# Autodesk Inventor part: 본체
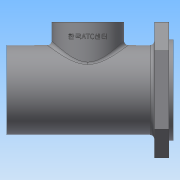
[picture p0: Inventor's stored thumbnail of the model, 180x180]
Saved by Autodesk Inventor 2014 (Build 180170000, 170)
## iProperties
Created: 2017-10
Part Number: 본체
Material: 일반
Document SubType Name: Modeling
Designer: net
Density: 1 g/cm^3
Appearance: 기본값
Mass: 274.888 g
Surface Area: 660.032 cm^2
Volume: 274.888 cm^3
Author: net
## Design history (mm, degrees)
sketch "스케치1"
  geometry: L1 (-58, 47)-(58, 47); L2 (58, 47)-(58, -47); L3 (58, -47)-(-58, -47); L4 (-58, -47)-(-58, 47); L5 (-46, 20)-(-46, -20); L6 (-42, 20)-(-42, -20); L7 (-50, -20)-(-50, 20); L8 (46, 20)-(46, -20); L9 (50, 20)-(50, -20); L10 (42, -20)-(42, 20); A1 r 4 centre (-46, 20) between (-42, 20) and (-50, 20); A2 r 4 centre (-46, -20) between (-50, -20) and (-42, -20); A3 r 4 centre (46, 20) between (50, 20) and (42, 20); A4 r 4 centre (46, -20) between (42, -20) and (50, -20); 5 further points
  constraints: 24 end point, 8 point on circle, 8 tangent, 7 parallel, 4 centre point, 4 midpoint, 3 horizontal alignment, 1 equal radius, 1 horizontal, 1 perpendicular, 1 vertical alignment
  dimensions: "d0" = 116 distance of L2.end L3.end; "d1" = 94 distance of L1.end L2.end; "d2" = 46 distance of point (0, 0) point (-46, 0); "d3" = 40 distance of L5.start L5.end; "d4" = 4 radius of A1; "d7" = 46 distance of point (46, 0) point (0, 0)
extrude "돌출1" new body sketch "스케치1" distance "d5" = 10; taper "d6" = 0 deg
extrude "돌출2" cut sketch "스케치1" stored distance "d8" = 10; taper "d9" = 0 deg
chamfer "모따기1" distance "d10" = 20; stored, may be unused: second distance "d11" = 2, angle "d12" = 45 deg
sketch "스케치2"
  geometry: C1 r 31 at (0, 0); 1 further point
  constraints: 1 centre point, 1 coincident
  dimensions: "d13" = 62 diameter of C1
extrude "돌출3" join sketch "스케치2" distance "d14" = 102; taper "d15" = 0 deg
sketch "스케치3"
  geometry: C1 r 35 at (0, 0); 1 further point
  constraints: 1 centre point, 1 coincident
  dimensions: "d16" = 70 diameter of C1
extrude "돌출4" join sketch "스케치3" distance "d17" = 3; taper "d18" = 0 deg
sketch "스케치4"
  geometry: L1 (31, 0)-(31, -102) reference; L2 (-31, -102)-(31, -102) reference; L3 (35, 13)-(-35, 13) reference; L4 (0, -102)-(0, 13); L5 (0, -93)-(24, -93); L6 (24, -93)-(24, -90); L7 (24, -90)-(20, -90); L8 (20, -90)-(20, -81); L9 (20, -81)-(17.5, -81); L10 (17.5, -81)-(17.5, -77.75); L11 (17.5, -77.75)-(18.5, -77.75); L12 (18.5, -77.75)-(18.5, -76); L13 (26, -65)-(26, -27); L14 (26, -27)-(17.5, -27); L15 (17.5, -27)-(17.5, -16); L16 (17.5, -16)-(16.5, -16); L17 (16.5, -16)-(16.5, -11); L18 (16.5, -11)-(10, -11); L19 (10, -11)-(10, -8.3); L20 (10, -8.3)-(12.5, -8.3); L21 (12.5, -8.3)-(12.5, -1.7); L22 (18.5, -76)-(17.5, -76); L23 (17.5, -76)-(17.5, -65); L24 (17.5, -65)-(26, -65); L25 (12.5, -1.7)-(12.904, -1); L26 (12.904, -1)-(16, -1); L27 (16, -1)-(22, 13); 2 further points
  constraints: 48 end point, 16 parallel, 3 midpoint, 3 perpendicular, 2 point on line, 1 horizontal
  dimensions: "d19" = 3 distance of L5.end L6.end; "d20" = 9 distance of L7.end L8.end; "d21" = 48 diameter of L6 L4; "d22" = 40 diameter of L8 L4; "d23" = 9 distance between parallel lines of L2 L5; "d24" = 35 diameter of L10 L4; "d25" = 37 diameter of L12 L4; "d28" = 3.25 distance of L9.end L10.end; "d29" = 38 distance of L13.start L13.end; "d30" = 52 diameter of L13 L4; "d31" = 35 diameter of L15 L4; "d32" = 11 distance of L14.end L15.end; "d33" = 2.7 distance of L18.end L19.end; "d35" = 20 diameter of L19 L4; "d36" = 25 diameter of L21 L4; "d39" = 33 diameter of L17 L4; "d40" = 5 distance of L16.end L17.end; "d42" = 1.75 distance of L11.end L12.end; "d43" = 11 distance of L22.end L23.end; "d44" = 35 diameter of L23 L4; "d47" = 0.7 vertical distance of L21.end L25.end; "d48" = 7.3 vertical distance of L25.end L20.end; "d50" = 32 diameter of L26.end L4; "d51" = 44 diameter of L27.end L4
revolve "회전1" sketch "스케치4" stored, may be unused: angle "d52" = 90 deg
hole "구멍1" diameter "d55" = 37.129; stored, may be unused: countersink angle "d59" = 90 deg, drill point angle "d61" = 118 deg; dims "d53" = 10, "d54" = 10, "d56" = 9, "d57" = 4, "d58" = 2, "d60" = 9
node "작업 평면1"
sketch "스케치5"
  geometry: L1 (38, 0)-(-38, 0) reference; L2 (-31, -102)-(31, -102) reference; C1 r 25 at (0, -46); C2 r 16 at (0, -46); 2 further points
  constraints: 2 centre point, 1 coincident, 1 midpoint, 1 vertical alignment
  dimensions: "d63" = 50 diameter of C1; "d64" = 32 diameter of C2; "d65" = 31 distance edge to line of C1 L2
extrude "돌출5" join sketch "스케치5" stored distance "d66" = 3; taper "d67" = 0 deg
extrude "돌출6" cut sketch "스케치5" stored distance "d68" = 3; taper "d69" = 0 deg
sketch "스케치6"
  geometry: C1 r 16 at (0, 0) reference; 3 further points
  constraints: 2 horizontal alignment
  dimensions: "d70" = 41 distance of point (20.5, 0) point (-20.5, 0); "d71" = 20.5 distance of point (-20.5, 0) C1.centre
hole "구멍2" sketch "스케치6" at (-20.5, 0), (20.5, 0) diameter "d72" = 2.459; stored, may be unused: countersink angle "d76" = 90 deg, drill point angle "d78" = 118 deg; dims "d73" = 6, "d74" = 4, "d75" = 2, "d77" = 8
node "작업 평면2"
sketch "스케치7"
  geometry: L1 (16, -56)-(78, -56) reference; L2 (0, -25)-(0, 25) reference; 2 further points
  constraints: 1 other
  dimensions: "d79" = 56 distance from line of L1 point (10, 0); "d80" = 10 distance from line of point (10, 0) L2
feature "엠보싱1" sketch "스케치7" dims "d0" = 116, "d1" = 94, "d2" = 46, "d3" = 40, "d4" = 4, "d7" = 46, "d81" = 0.5, "d82" = 0
fillet "모깎기1" dims "d83" = 0.3
fillet "모깎기2" dims "d84" = 0.3
fillet "모깎기3" dims "d85" = 3
fillet "모깎기4" dims "d86" = 3
fillet "모깎기5" dims "d87" = 3
chamfer "모따기2" distance "d88" = 1; stored, may be unused: second distance "d89" = 2, angle "d90" = 45 deg
fillet "모깎기6" dims "d91" = 3
node "솔리드1"
other parameters: "d62" = 47
